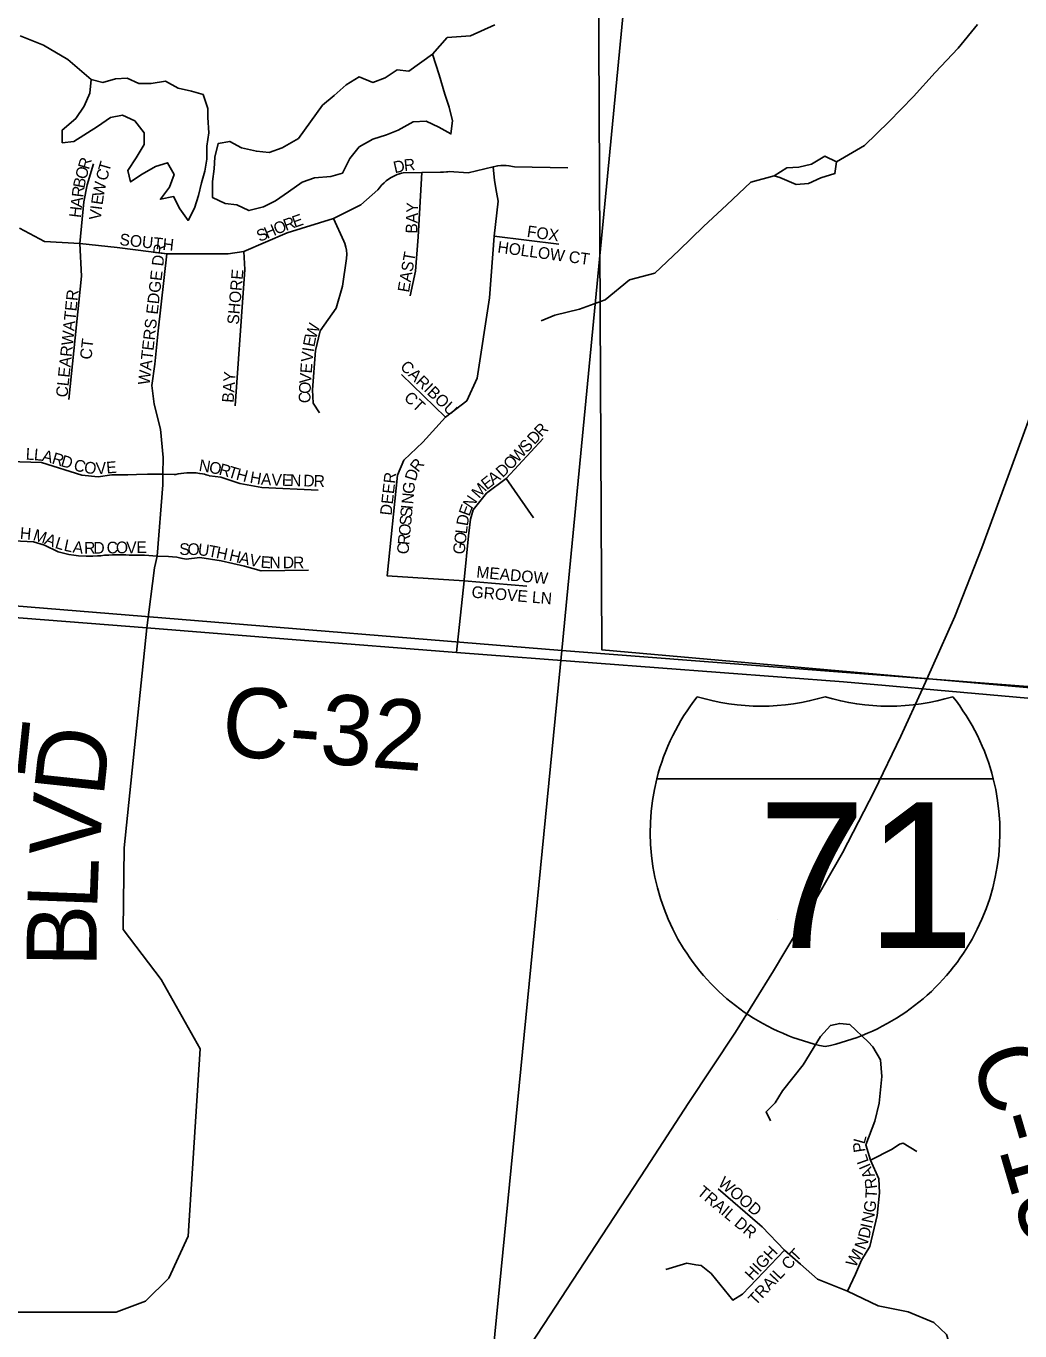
# Model space of a CAD drawing. Extents: x 0 to 1064, y 0 to 440.
# Drawn here: x 159.59 to 172.51, y 107.1 to 124.05 of the extents above; entities that cross this region are included whole.
import ezdxf

# ---------------------------------------------------------------- set-up
doc = ezdxf.new("R2010")
doc.units = 0
for name, color, linetype in [('GM_X_Corporation', 7, 'Continuous'), ('GM_X_County_Road', 7, 'Continuous'), ('GM_X_County_Road_Text', 7, 'Continuous'), ('GM_X_Interstate_Location', 7, 'Continuous'), ('GM_X_Interstate_Route', 7, 'Continuous'), ('GM_X_Interstate_Shield', 7, 'Continuous'), ('GM_X_Minor_Lake', 7, 'Continuous'), ('GM_X_Minor_River', 7, 'Continuous'), ('GM_X_Section', 7, 'Continuous'), ('GM_X_Township_Subdivision', 7, 'Continuous'), ('GM_X_Township_Subdivision_Text', 7, 'Continuous')]:
    doc.layers.add(name, color=color, linetype=linetype)

msp = doc.modelspace()

# ---------------------------------------------------------------- linework, layer by layer
at = {"layer": 'GM_X_Corporation'}
msp.add_lwpolyline([(176.201, 124.373), (175.606, 119.781), (175.563, 119.506), (175.5, 119.337), (174.988, 118.195), (174.334, 116.544), (173.92, 115.338), (167.075, 115.945), (167.031, 124.73)], dxfattribs=at)
at = {"layer": 'GM_X_County_Road'}
for points in [[(158.22, 116.461), (160.662, 116.269)], [(159.41, 107.338), (160.761, 107.341), (161.144, 107.482), (161.445, 107.783), (161.697, 108.325), (161.854, 110.759), (161.349, 111.662), (160.855, 112.313), (160.867, 113.373), (161.163, 116.23)], [(160.662, 116.269), (161.163, 116.23), (163.103, 116.075)], [(163.103, 116.075), (165.185, 115.909), (167.01, 115.771)], [(167.01, 115.771), (170.217, 115.528), (170.761, 115.48), (171.241, 115.437), (173.981, 115.194)]]:
    msp.add_lwpolyline(points, dxfattribs=at)
at = {"layer": 'GM_X_Interstate_Route'}
for points in [[(171.372, 115.73), (171.661, 116.377), (172.013, 117.27), (172.405, 118.332), (172.779, 119.364), (173.12, 120.375), (173.551, 121.781), (173.87, 122.826), (174.216, 124.017), (174.282, 124.239)], [(165.607, 106.093), (166.322, 107.179), (167.074, 108.33), (167.651, 109.212), (168.197, 110.052), (168.811, 110.976), (169.307, 111.774), (169.76, 112.537), (170.201, 113.306), (170.619, 114.113), (170.961, 114.823), (171.241, 115.437), (171.372, 115.73)]]:
    msp.add_lwpolyline(points, dxfattribs=at)
at = {"layer": 'GM_X_Interstate_Shield'}
for p, q in [((167.79, 114.271), (172.162, 114.271)), ((172.162, 114.271), (167.79, 114.271)), ((172.162, 114.271), (167.79, 114.271))]:
    msp.add_line(p, q, dxfattribs=at)
for centre, start, end in [((170.544, 113.574), 141.669, 165.8066), ((169.146, 118.053), 253.0091, 286.9909), ((170.806, 118.053), 253.0091, 286.9909), ((169.408, 113.574), 14.1934, 38.331), ((170.544, 113.574), 165.8066, 258.463), ((169.408, 113.574), 281.537, 14.1934)]:
    msp.add_arc(centre, 2.841, start, end, dxfattribs=at)
at = {"layer": 'GM_X_Minor_Lake'}
for points in [[(164.874, 123.685), (164.567, 123.463), (164.415, 123.481), (164.257, 123.378), (164.099, 123.317), (163.922, 123.39), (163.752, 123.287), (163.594, 123.147), (163.442, 123.02), (163.132, 122.588), (162.919, 122.467), (162.749, 122.406), (162.585, 122.424), (162.39, 122.467), (162.238, 122.552), (162.086, 122.522), (162.044, 122.345), (162.038, 122.194), (162.013, 122.03), (162.013, 121.823), (162.177, 121.744), (162.329, 121.726), (162.488, 121.653), (162.676, 121.702), (162.834, 121.781), (163.004, 121.896), (163.182, 122.02)], [(163.182, 122.02), (163.339, 122.078), (163.551, 122.096), (163.703, 122.139), (163.801, 122.327), (163.922, 122.479), (164.099, 122.582), (164.275, 122.637), (164.427, 122.698), (164.621, 122.807), (164.792, 122.813), (164.956, 122.734), (165.114, 122.649), (165.132, 122.819), (165.09, 122.995), (165.035, 123.166), (164.962, 123.415), (164.874, 123.685)], [(160.439, 123.354), (160.42, 123.178), (160.347, 123.008), (160.238, 122.85), (160.062, 122.698), (160.062, 122.534), (160.214, 122.552), (160.518, 122.746), (160.688, 122.862), (160.846, 122.892), (161.004, 122.819), (161.126, 122.661), (161.126, 122.51), (161.022, 122.339), (160.913, 122.175), (160.949, 122.024), (161.101, 122.127), (161.272, 122.224), (161.43, 122.273), (161.515, 122.121), (161.454, 121.957), (161.338, 121.799), (161.509, 121.835), (161.588, 121.677), (161.697, 121.525), (161.782, 121.683), (161.831, 121.847), (161.873, 122.011), (161.916, 122.163), (161.94, 122.321), (161.94, 122.491), (161.965, 122.661), (161.952, 122.862)], [(161.952, 122.862), (161.952, 122.977), (161.892, 123.159), (161.74, 123.202), (161.569, 123.245), (161.405, 123.336), (161.217, 123.305), (161.059, 123.305), (160.907, 123.372), (160.755, 123.366), (160.591, 123.317), (160.439, 123.354)], [(169.923, 122.079), (170.105, 122.133), (170.124, 122.285), (169.972, 122.358), (169.801, 122.254), (169.637, 122.218), (169.479, 122.206), (169.315, 122.102)], [(169.315, 122.102), (169.388, 122.084), (169.601, 121.993), (169.759, 122.005), (169.923, 122.079)]]:
    msp.add_lwpolyline(points, dxfattribs=at)
at = {"layer": 'GM_X_Minor_River'}
for points in [[(165.685, 124.065), (165.369, 123.925), (165.065, 123.901), (164.874, 123.685)], [(171.959, 124.071), (171.704, 123.761), (171.406, 123.445), (171.127, 123.135), (170.804, 122.807), (170.488, 122.497), (170.124, 122.285)], [(160.439, 123.354), (160.135, 123.615), (159.818, 123.803), (159.514, 123.925)], [(169.315, 122.102), (169.011, 122.023), (168.701, 121.726), (168.397, 121.446), (168.081, 121.137), (167.765, 120.839), (167.436, 120.754), (167.12, 120.493), (166.786, 120.371), (166.464, 120.292), (166.287, 120.219)]]:
    msp.add_lwpolyline(points, dxfattribs=at)
at = {"layer": 'GM_X_Section'}
for points in [[(151.892, 133.436), (168.142, 132.406), (166.556, 115.937), (150.318, 117.263)], [(168.142, 132.406), (184.27, 131.039), (182.704, 114.691), (166.556, 115.937)], [(150.318, 117.263), (166.556, 115.937), (164.917, 99.233), (148.691, 100.849)], [(166.556, 115.937), (182.704, 114.691), (180.995, 96.285), (164.917, 99.233)]]:
    msp.add_lwpolyline(points, close=True, dxfattribs=at)
at = {"layer": 'GM_X_Township_Subdivision'}
for points in [[(159.507, 121.426), (159.83, 121.252), (160.288, 121.223), (160.776, 121.174), (161.422, 121.091), (161.85, 121.091), (162.218, 121.091), (162.421, 121.121), (162.985, 121.362), (163.585, 121.55), (163.942, 121.728), (164.164, 121.922), (164.185, 121.95), (164.213, 121.984), (164.244, 122.015), (164.27, 122.037), (164.3, 122.059), (164.335, 122.082), (164.371, 122.101), (164.413, 122.119), (164.445, 122.131), (164.471, 122.139), (164.494, 122.144), (164.735, 122.149), (164.978, 122.152), (165.019, 122.152), (165.057, 122.154), (165.075, 122.156), (165.089, 122.158), (165.336, 122.141), (165.663, 122.222), (165.721, 122.234), (165.76, 122.239), (165.801, 122.24), (165.83, 122.239), (165.868, 122.235), (165.938, 122.221), (166.635, 122.209)], [(160.288, 121.223), (160.34, 121.764), (160.385, 121.989), (160.468, 122.26)], [(165.284, 116.843), (164.284, 116.908), (164.419, 118.215), (164.502, 118.411), (164.75, 118.644), (165.043, 118.97), (165.321, 119.181), (165.456, 119.474), (165.614, 120.518), (165.674, 121.322), (165.726, 121.773), (165.704, 121.893), (165.681, 122.044), (165.663, 122.222)], [(164.584, 120.544), (164.652, 120.864), (164.686, 121.311), (164.735, 122.149)], [(163.405, 119.025), (163.323, 119.151), (163.315, 119.325), (163.353, 119.836), (163.413, 120.092), (163.623, 120.385), (163.706, 120.67), (163.758, 121.028), (163.759, 121.087), (163.754, 121.137), (163.746, 121.179), (163.734, 121.225), (163.722, 121.256), (163.585, 121.55)], [(160.149, 119.198), (160.31, 120.802), (160.288, 121.223)], [(165.674, 121.322), (166.515, 121.217)], [(161.163, 116.23), (161.261, 117.011), (161.294, 117.16), (161.368, 118.088), (161.37, 118.228), (161.373, 118.444), (161.339, 118.813), (161.257, 119.138), (161.227, 119.378), (161.264, 119.656), (161.309, 120.092), (161.422, 121.091)], [(162.308, 119.115), (162.436, 120.888), (162.421, 121.121)], [(165.043, 118.97), (164.471, 119.523)], [(165.285, 116.855), (165.343, 117.426), (165.366, 117.644), (165.403, 117.764), (165.576, 117.982), (165.831, 118.17), (166.312, 118.689)], [(159.086, 118.401), (159.792, 118.378), (160.318, 118.213), (160.528, 118.191), (160.708, 118.221), (160.916, 118.217), (161.028, 118.223), (161.17, 118.228), (161.37, 118.228)], [(161.37, 118.228), (161.516, 118.222), (161.538, 118.223), (161.569, 118.23), (161.606, 118.237), (161.64, 118.242), (161.682, 118.246), (161.713, 118.247), (161.755, 118.247), (161.784, 118.246), (161.803, 118.244), (161.825, 118.241), (161.847, 118.238), (161.883, 118.232), (161.909, 118.226), (161.933, 118.22), (161.968, 118.209), (161.972, 118.208), (161.977, 118.207), (162.123, 118.19), (162.369, 118.108), (162.654, 118.056), (163.39, 118.018)], [(165.831, 118.17), (166.185, 117.659)], [(159.437, 117.362), (159.687, 117.348), (159.83, 117.303), (160.007, 117.217), (160.078, 117.199), (160.146, 117.185), (160.213, 117.175), (160.274, 117.168), (160.374, 117.161), (160.458, 117.161), (160.521, 117.165), (160.562, 117.168), (160.609, 117.173), (160.666, 117.177), (160.713, 117.18), (160.799, 117.181), (160.889, 117.179), (160.93, 117.177), (160.963, 117.175), (160.982, 117.173), (161.016, 117.174), (161.131, 117.176), (161.294, 117.16)], [(161.294, 117.16), (161.443, 117.159), (161.494, 117.154), (161.55, 117.148), (161.605, 117.138), (161.674, 117.123), (161.85, 117.145), (162.128, 117.1), (162.429, 117.032), (162.646, 116.972), (163.262, 116.979)], [(165.185, 115.909), (165.284, 116.843), (165.285, 116.855)], [(165.284, 116.843), (166.102, 116.773)], [(170.267, 107.612), (170.372, 107.832), (170.451, 108.016), (170.559, 108.192), (170.653, 108.594), (170.685, 108.889), (170.677, 109.073), (170.566, 109.314), (170.508, 109.512), (170.621, 109.819), (170.68, 110.056), (170.716, 110.402), (170.695, 110.616), (170.597, 110.785), (170.535, 110.852), (170.297, 111.075), (170.167, 111.092), (170.046, 111.064), (169.919, 110.923), (169.691, 110.552), (169.423, 110.216), (169.328, 110.061), (169.209, 109.943), (169.266, 109.825)], [(170.566, 109.314), (170.85, 109.458), (170.945, 109.521), (170.993, 109.537), (171.168, 109.426)], [(169.129, 108.474), (168.585, 108.943)], [(171.637, 106.492), (171.629, 106.817), (171.555, 107.051), (171.392, 107.204), (171.055, 107.343), (170.668, 107.421), (170.267, 107.612), (169.876, 107.768), (169.656, 107.961), (169.448, 108.145), (169.16, 108.447), (169.129, 108.474)], [(168.298, 107.955), (168.365, 107.944), (168.494, 107.843), (168.779, 107.493), (168.905, 107.571), (169.448, 108.145)], [(167.906, 107.893), (168.178, 107.975), (168.298, 107.955)]]:
    msp.add_lwpolyline(points, dxfattribs=at)

# ---------------------------------------------------------------- texts
at = {"layer": 'GM_X_County_Road_Text'}
for s, height, rotation, p in [('C-32', 0.9091, 355.5233, (162.113, 114.575)), ('E', 0.909, 84.0924, (159.567, 114.241)), ('D', 0.909, 83.8903, (160.598, 114.021)), ('V', 0.909, 85.6938, (160.538, 113.23)), ('L', 0.909, 87.8567, (160.514, 112.56)), ('B', 0.909, 89.3872, (160.506, 111.82)), ('C-15', 0.9091, 286.3705, (171.868, 110.691))]:
    msp.add_text(s, height=height, rotation=rotation, dxfattribs=at).set_placement(p)
at = {"layer": 'GM_X_Interstate_Location'}
for s in ['-', '.', ',']:
    msp.add_text(s, height=0.00303, dxfattribs=at).set_placement((169.975, 113.062))
msp.add_text('71', height=0.00303, rotation=0, dxfattribs=at).set_placement((169.356, 112.434))
at = {"layer": 'GM_X_Interstate_Shield'}
msp.add_text('71', height=1.8939, dxfattribs=at).set_placement((169.101, 112.069))
at = {"layer": 'GM_X_Township_Subdivision_Text'}
for s, height, rotation, p in [('R', 0.152, 73.731, (160.408, 122.177)), ('T', 0.152, 73.6644, (160.671, 122.145)), ('D', 0.152, 12.9176, (164.384, 122.136)), ('R', 0.152, 5.6913, (164.509, 122.165)), ('B', 0.152, 78.5567, (160.348, 121.934)), ('O', 0.152, 74.0126, (160.371, 122.049)), ('C', 0.152, 75.0686, (160.641, 122.03)), ('R', 0.152, 83.0202, (160.334, 121.818)), ('W', 0.152, 79.0033, (160.599, 121.823)), ('A', 0.152, 82.9888, (160.318, 121.686)), ('E', 0.152, 81.8042, (160.585, 121.72)), ('BAY', 0.1515, 88.0261, (164.675, 121.351)), ('H', 0.152, 83.0105, (160.301, 121.553)), ('V', 0.152, 83.0756, (160.56, 121.522)), ('I', 0.152, 82.8099, (160.576, 121.654)), ('R', 0.152, 19.925, (162.968, 121.386)), ('E', 0.152, 19.1263, (163.08, 121.427)), ('S', 0.152, 22.8721, (162.625, 121.243)), ('H', 0.152, 22.8891, (162.724, 121.284)), ('O', 0.152, 22.4063, (162.846, 121.336)), ('FOX', 0.1515, 351.8666, (166.094, 121.311)), ('SOUTH', 0.1515, 353.7949, (160.8, 121.205)), ('HOLLOW CT', 0.1515, 352.2681, (165.712, 121.107)), ('WATERS EDGE DR', 0.15152, 83.4007, (161.195, 119.38)), ('EAST', 0.1515, 80.2705, (164.568, 120.582)), ('SHORE', 0.1515, 85.028, (162.355, 120.166)), ('CLEARWATER', 0.1515, 83.9918, (160.128, 119.22)), ('W', 0.152, 71.044, (163.356, 119.973)), ('CT', 0.1515, 83.6638, (160.44, 119.711)), ('I', 0.152, 81.7957, (163.328, 119.809)), ('E', 0.152, 78.7812, (163.337, 119.873)), ('V', 0.152, 84.8788, (163.316, 119.679)), ('BAY', 0.1515, 86.0494, (162.288, 119.152)), ('V', 0.152, 85.5376, (163.294, 119.4)), ('E', 0.152, 85.4315, (163.304, 119.533)), ('CARIBOU', 0.1515, 316.2723, (164.443, 119.611)), ('O', 0.152, 87.4203, (163.288, 119.268)), ('C', 0.152, 89.8543, (163.288, 119.15)), ('CT', 0.1515, 317.2983, (164.492, 119.206)), ('R', 0.152, 46.7347, (166.29, 118.7)), ('S', 0.152, 46.7327, (166.098, 118.496)), ('D', 0.152, 46.7469, (166.198, 118.603)), ('L', 0.152, 356.5549, (159.584, 118.417)), ('L', 0.152, 354.5558, (159.689, 118.411)), ('A', 0.152, 345.7358, (159.789, 118.402)), ('R', 0.152, 343.324, (159.917, 118.369)), ('W', 0.152, 46.7411, (165.979, 118.37)), ('D', 0.152, 343.307, (160.032, 118.335)), ('C', 0.152, 343.31, (160.198, 118.285)), ('O', 0.152, 352.6434, (160.339, 118.245)), ('V', 0.152, 3.3422, (160.502, 118.227)), ('E', 0.152, 4.8943, (160.64, 118.235)), ('N', 0.152, 350.3364, (161.83, 118.272)), ('O', 0.152, 348.27, (161.96, 118.25)), ('R', 0.152, 344.7151, (162.088, 118.224)), ('R', 0.152, 51.78, (164.687, 118.243)), ('D', 0.152, 43.168, (165.783, 118.174)), ('O', 0.152, 46.6889, (165.888, 118.273)), ('T', 0.152, 343.2327, (162.203, 118.192)), ('H', 0.152, 345.3171, (162.311, 118.16)), ('H', 0.152, 350.0347, (162.492, 118.116)), ('A', 0.152, 356.1532, (162.641, 118.091)), ('V', 0.152, 358.3151, (162.78, 118.081)), ('E', 0.152, 358.3479, (162.914, 118.077)), ('N', 0.152, 358.3385, (163.02, 118.074)), ('D', 0.152, 358.3377, (163.193, 118.069)), ('R', 0.152, 358.3428, (163.327, 118.065)), ('DEER', 0.1515, 83.6571, (164.341, 117.686)), ('D', 0.152, 72.5534, (164.654, 118.129)), ('E', 0.152, 38.1265, (165.58, 118.017)), ('A', 0.152, 37.1103, (165.663, 118.083)), ('G', 0.152, 83.5826, (164.633, 117.965)), ('M', 0.152, 48.2984, (165.479, 117.903)), ('N', 0.152, 84.6374, (164.621, 117.833)), ('E', 0.152, 69.8021, (165.352, 117.672)), ('N', 0.152, 56.3887, (165.384, 117.764)), ('S', 0.152, 84.7574, (164.595, 117.554)), ('S', 0.152, 84.7574, (164.605, 117.66)), ('I', 0.152, 84.7027, (164.615, 117.766)), ('D', 0.152, 80.6706, (165.332, 117.548)), ('H', 0.152, 355.2291, (159.507, 117.388)), ('M', 0.152, 342.1755, (159.671, 117.374)), ('O', 0.152, 84.745, (164.583, 117.421)), ('L', 0.152, 83.18, (165.32, 117.444)), ('A', 0.152, 337.671, (159.82, 117.326)), ('L', 0.152, 342.7222, (159.957, 117.271)), ('L', 0.152, 348.0048, (160.074, 117.235)), ('A', 0.152, 352.7801, (160.192, 117.211)), ('R', 0.152, 0.8133, (160.347, 117.193)), ('D', 0.152, 0.8088, (160.467, 117.194)), ('C', 0.152, 0.7896, (160.64, 117.197)), ('O', 0.152, 0.8036, (160.76, 117.199)), ('V', 0.152, 0.8036, (160.894, 117.2)), ('E', 0.152, 0.8115, (161.027, 117.202)), ('S', 0.152, 359.8087, (161.583, 117.178)), ('O', 0.152, 359.2568, (161.689, 117.178)), ('U', 0.152, 352.6364, (161.818, 117.177)), ('C', 0.152, 84.7462, (164.561, 117.182)), ('R', 0.152, 84.722, (164.572, 117.301)), ('G', 0.152, 83.165, (165.288, 117.179)), ('O', 0.152, 83.1755, (165.304, 117.311)), ('T', 0.152, 349.3115, (161.948, 117.16)), ('H', 0.152, 348.4029, (162.052, 117.14)), ('H', 0.152, 347.1037, (162.221, 117.105)), ('A', 0.152, 347.1584, (162.351, 117.075)), ('V', 0.152, 347.684, (162.482, 117.045)), ('E', 0.152, 355.9366, (162.636, 117.013)), ('N', 0.152, 359.9028, (162.754, 117.005)), ('D', 0.152, 359.9929, (162.928, 117.005)), ('R', 0.152, 359.9941, (163.061, 117.005)), ('MEADOW', 0.1515, 354.6436, (165.439, 116.885)), ('GROVE LN', 0.1515, 355.1005, (165.377, 116.625)), ('P', 0.152, 98.3079, (170.503, 109.426)), ('L', 0.152, 74.2609, (170.487, 109.515)), ('L', 0.152, 109.5234, (170.547, 109.295)), ('I', 0.152, 113.1412, (170.573, 109.236)), ('A', 0.152, 113.8411, (170.626, 109.114)), ('WOOD', 0.1515, 319.6836, (168.575, 108.998)), ('R', 0.152, 97.5811, (170.655, 108.95)), ('TRAIL DR', 0.1515, 320.0814, (168.301, 108.879)), ('T', 0.152, 86.4818, (170.649, 108.812)), ('G', 0.152, 81.987, (170.625, 108.627)), ('N', 0.152, 78.2227, (170.596, 108.486)), ('D', 0.152, 77.1231, (170.55, 108.287)), ('I', 0.152, 76.9497, (170.58, 108.417)), ('HIGH', 0.1515, 47.2937, (169.029, 107.743)), ('TRAIL CT', 0.1515, 46.9294, (169.073, 107.418)), ('I', 0.152, 61.6168, (170.454, 108.063)), ('N', 0.152, 68.4597, (170.494, 108.139)), ('W', 0.152, 61.6002, (170.371, 107.91))]:
    msp.add_text(s, height=height, rotation=rotation, dxfattribs=at).set_placement(p)

doc.saveas('drawing.dxf')
